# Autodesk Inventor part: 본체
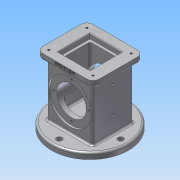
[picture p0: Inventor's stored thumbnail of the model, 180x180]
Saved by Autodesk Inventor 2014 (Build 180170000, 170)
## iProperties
Created: 2018-10
Part Number: 본체
Material: 알루미늄 6061
Document SubType Name: Modeling
Designer: Administrator
Density: 2.71 g/cm^3
Appearance: 알루미늄 - 평지
Mass: 988.221 g
Surface Area: 743.905 cm^2
Volume: 364.657 cm^3
Author: Administrator
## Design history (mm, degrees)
sketch "스케치1"
  geometry: C1 r 62.5 at (0, 0); 1 further point
  constraints: 1 centre point, 1 coincident
  dimensions: "d0" = 125 diameter of C1
extrude "돌출1" new body sketch "스케치1" distance "d1" = 10; taper "d2" = 0 deg
sketch "스케치2"
  geometry: L1 (-37, -33)-(37, -33); L2 (37, -33)-(37, 33); L3 (37, 33)-(-37, 33); L4 (-37, 33)-(-37, -33); L5 (-37, -33)-(37, 33); L6 (37, -33)-(-37, 33); 3 further points
  constraints: 12 end point, 3 midpoint, 2 parallel, 1 coincident, 1 horizontal, 1 perpendicular
  dimensions: "d3" = 74 distance of L3.end L2.end; "d4" = 66 distance of L2.end L1.end
extrude "돌출2" join sketch "스케치2" distance "d5" = 88; taper "d6" = 0 deg
sketch "스케치3"
  geometry: L1 (-46, -41)-(46, -41); L2 (46, -41)-(46, 41); L3 (46, 41)-(-46, 41); L4 (-46, 41)-(-46, -41); L5 (-46, -41)-(46, 41); L6 (46, -41)-(-46, 41); 3 further points
  constraints: 12 end point, 3 midpoint, 2 parallel, 1 coincident, 1 horizontal, 1 perpendicular
  dimensions: "d7" = 92 distance of L3.end L2.end; "d8" = 82 distance of L2.end L1.end
extrude "돌출3" join sketch "스케치3" distance "d9" = 10; taper "d10" = 0 deg
fillet "모깎기1" dims "d11" = 10
sketch "스케치4"
  geometry: L1 (-26, -26)-(26, -26); L2 (26, -26)-(26, 26); L3 (26, 26)-(-26, 26); L4 (-26, 26)-(-26, -26); L5 (-26, -26)-(26, 26); L6 (26, -26)-(-26, 26); 3 further points
  constraints: 12 end point, 3 midpoint, 2 parallel, 1 coincident, 1 horizontal, 1 perpendicular
  dimensions: "d12" = 52 distance of L3.end L2.end; "d13" = 52 distance of L2.end L1.end
extrude "돌출4" cut sketch "스케치4" distance "d14" = 8; taper "d15" = 0 deg
sketch "스케치5"
  geometry: L1 (-22, -22)-(22, -22); L2 (22, -22)-(22, 22); L3 (22, 22)-(-22, 22); L4 (-22, 22)-(-22, -22); L5 (-22, -22)-(22, 22); L6 (22, -22)-(-22, 22); 3 further points
  constraints: 12 end point, 3 midpoint, 2 parallel, 1 coincident, 1 horizontal, 1 perpendicular
  dimensions: "d16" = 44 distance of L3.end L2.end; "d17" = 44 distance of L2.end L1.end
sketch "스케치7"
  geometry: L1 (-25.5, -10)-(99.5, -10) reference; C1 r 35 at (37, 44); 2 further points
  constraints: 1 centre point, 1 midpoint, 1 vertical alignment
  dimensions: "d18" = 70 diameter of C1; "d19" = 54 distance from line of C1.centre L1
extrude "돌출5" cut sketch "스케치7" distance "d20" = 3; taper "d21" = 0 deg
extrude "돌출6" cut sketch "스케치5" distance "d22" = 74; taper "d23" = 0 deg
sketch "스케치9"
  geometry: C1 r 24 at (0, 0); 1 further point
  constraints: 1 centre point, 1 vertical alignment
  dimensions: "d24" = 54 distance of C1.centre point (0, -54); "d25" = 48 diameter of C1
extrude "돌출7" cut sketch "스케치9" stored distance "d26" = 74; taper "d27" = 0 deg
sketch "스케치11"
  geometry: C1 r 28 at (0, 0); 1 further point
  constraints: 1 centre point, 1 coincident
  dimensions: "d28" = 56 diameter of C1
extrude "돌출8" cut sketch "스케치11" distance "d29" = 18; taper "d30" = -10 deg
chamfer "모따기1" distance "d31" = 1; stored, may be unused: second distance "d32" = 2, angle "d33" = 45 deg
fillet "모깎기2" dims "d34" = 3
fillet "모깎기3" dims "d35" = 3
fillet "모깎기4" dims "d36" = 3
fillet "모깎기5" dims "d37" = 3
fillet "모깎기6" dims "d38" = 3
fillet "모깎기7" dims "d39" = 3
fillet "모깎기8" dims "d40" = 3
sketch "스케치12"
  geometry: L1 (40, -44)-(51.383, -44) reference; L2 (54.829, -47)-(54.829, -54) reference; L3 (54.829, -54)-(-54.829, -54) reference; L4 (-54.829, -54)-(-54.829, -47) reference; L5 (-51.383, -44)-(-40, -44) reference; L6 (-37, -41)-(-37, 41) reference; L7 (-40, 44)-(-43, 44) reference; L8 (-46, 47)-(-46, 54) reference; L9 (-46, 54)-(46, 54) reference; L10 (46, 54)-(46, 47) reference; L11 (43, 44)-(40, 44) reference; L12 (37, 41)-(37, -41) reference; C1 r 35 at (0, 0) reference; C2 r 24 at (0, 0) reference; A1 r 3 centre (40, -41) between (37, -41) and (40, -44) reference; A2 r 3 centre (-40, -41) between (-40, -44) and (-37, -41) reference; A3 r 3 centre (-40, 41) between (-37, 41) and (-40, 44) reference; A4 r 3 centre (-43, 47) between (-46, 47) and (-43, 44) reference; A5 r 3 centre (43, 47) between (43, 44) and (46, 47) reference; A6 r 3 centre (40, 41) between (40, 44) and (37, 41) reference; 2 further points
  constraints: 1 vertical alignment, 2 other
  dimensions: "d43" = 29 distance of C2.centre point (0, 29)
hole "구멍1" sketch "스케치12" at (0, 29) diameter "d44" = 3.242; stored, may be unused: countersink angle "d48" = 90 deg, drill point angle "d50" = 118 deg; dims "d45" = 4, "d46" = 4, "d47" = 2, "d49" = 6
sketch "스케치13"
  geometry: 2 further points
  constraints: 1 vertical alignment
  dimensions: "d55" = 50 distance of point (0, 50) point (0, 0)
hole "구멍2" sketch "스케치13" at (0, 50) diameter "d56" = 9; stored, may be unused: countersink angle "d60" = 90 deg, drill point angle "d62" = 118 deg; dims "d57" = 4, "d58" = 4, "d59" = 2, "d61" = 6
sketch "스케치14"
  geometry: L1 (95, -32.5)-(95, 92.5) reference; 3 further points
  constraints: 2 horizontal alignment
  dimensions: "d66" = 37 distance from line of L1 point (58, 30); "d67" = 43 distance of point (58, 30) point (15, 30)
hole "구멍3" sketch "스케치14" at (58, 30), (15, 30) diameter "d68" = 4.134; stored, may be unused: countersink angle "d72" = 90 deg, drill point angle "d74" = 118 deg; dims "d69" = 4, "d70" = 4, "d71" = 2, "d73" = 30
sketch "스케치15" dims "d25" = 48
  geometry: L1 (-10, 0)-(-10, -7) reference; L2 (72, -7)-(0, -7) reference; 2 further points
  constraints: 1 other
  dimensions: "d75" = 4 distance from line of L2 point (36, -3); "d76" = 46 distance from line of L1 point (36, -3)
feature "엠보싱1" sketch "스케치15" dims "d77" = 0.5, "d78" = 0
sketch "스케치16"
  geometry: 2 further points
  dimensions: "d79" = 31 vertical distance of point (-36, 31) point (0, 0); "d80" = 36 horizontal distance of point (0, 0) point (-36, 31)
hole "구멍4" sketch "스케치16" at (-36, 31) diameter "d81" = 3.242; stored, may be unused: countersink angle "d85" = 90 deg, drill point angle "d87" = 118 deg; dims "d82" = 4, "d83" = 4, "d84" = 2, "d86" = 6
node "솔리드1"
mirror "대칭1"
pattern_circular "원형 패턴1" dims angle "d52" = 360 deg
mirror "대칭2"
pattern_circular "원형 패턴2" dims angle "d64" = 360 deg
mirror "대칭3"
mirror "대칭4"
node "절단 모서리 투영1"
